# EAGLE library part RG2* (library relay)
HIGH FREQUENCY RELAYS WITH 1C AND 2C CONTACTS NAiS Source: http://www.mew-europe.com/.. en_ds_61302_0000.pdf
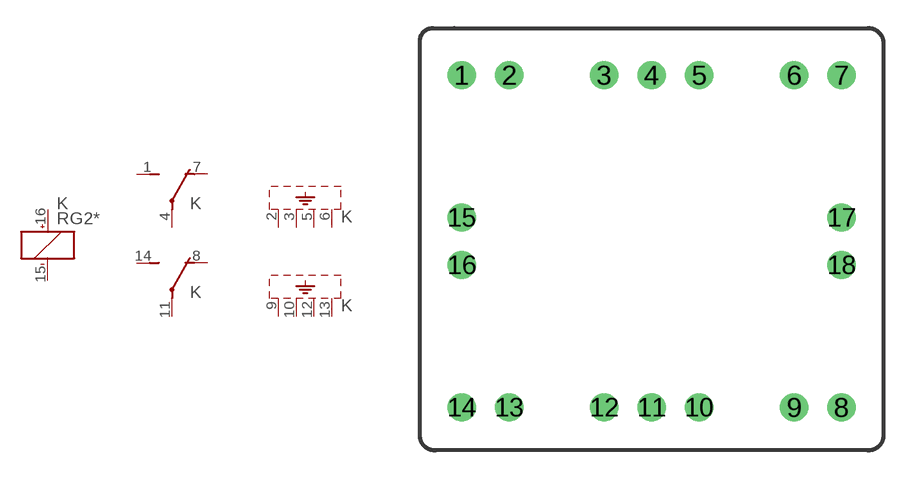
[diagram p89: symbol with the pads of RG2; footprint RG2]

Designator prefix K; gates A=K+- 1=U 2=U S1=SHIELD-4 S2=SHIELD-4

## RG2-3V (OC_FARNELL: unknown; OC_NEWARK: unknown), RG2-5V (OC_FARNELL: unknown; OC_NEWARK: unknown), RG2-6V (OC_FARNELL: unknown; OC_NEWARK: unknown), RG2-9V (OC_FARNELL: unknown; OC_NEWARK: unknown), RG2-12V (OC_FARNELL: unknown; OC_NEWARK: unknown), RG2-24V (OC_FARNELL: unknown; OC_NEWARK: unknown), RG2-48V (OC_FARNELL: unknown; OC_NEWARK: unknown), RG2T-3V (OC_FARNELL: unknown; OC_NEWARK: unknown), RG2T-5V (OC_FARNELL: unknown; OC_NEWARK: unknown), RG2T-6V (OC_FARNELL: unknown; OC_NEWARK: unknown), RG2T-9V (OC_FARNELL: unknown; OC_NEWARK: unknown), RG2T-12V (OC_FARNELL: unknown; OC_NEWARK: unknown), RG2T-24V (OC_FARNELL: unknown; OC_NEWARK: unknown), RG2T-48V (OC_FARNELL: unknown; OC_NEWARK: unknown)  [RG2]
1  1:S  pas
2  S1:SH  pas
3  S1:SH  pas
4  1:P  pas
5  S1:SH  pas
6  S1:SH  pas
7  1:O  pas
8  2:O  pas
9  S2:SH  pas
10  S2:SH  pas
11  2:P  pas
12  S2:SH  pas
13  S2:SH  pas
14  2:S  pas
15  A:-  pas
16  A:+  pas

## RG2-3V-L (OC_FARNELL: unknown; OC_NEWARK: unknown), RG2-5V-L (OC_FARNELL: unknown; OC_NEWARK: unknown), RG2-6V-L (OC_FARNELL: unknown; OC_NEWARK: unknown), RG2-9V-L (OC_FARNELL: unknown; OC_NEWARK: unknown), RG2-12V-L (OC_FARNELL: unknown; OC_NEWARK: unknown), RG2-24V-L (OC_FARNELL: unknown; OC_NEWARK: unknown), RG2-48V-L (OC_FARNELL: unknown; OC_NEWARK: unknown)  [RG2]
1  1:S  pas
2  S1:SH  pas
3  S1:SH  pas
4  1:P  pas
5  S1:SH  pas
6  S1:SH  pas
7  1:O  pas
8  2:O  pas
9  S2:SH  pas
10  S2:SH  pas
11  2:P  pas
12  S2:SH  pas
13  S2:SH  pas
14  2:S  pas
15  A:+  pas
16  A:-  pas

## RG2-3VT-L (OC_FARNELL: unknown; OC_NEWARK: unknown), RG2-5VT-L (OC_FARNELL: unknown; OC_NEWARK: unknown), RG2-6VT-L (OC_FARNELL: unknown; OC_NEWARK: unknown), RG2-9VT-L (OC_FARNELL: unknown; OC_NEWARK: unknown), RG2-12VT-L (OC_FARNELL: unknown; OC_NEWARK: unknown), RG2-24VT-L (OC_FARNELL: unknown; OC_NEWARK: unknown), RG2-48VT-L (OC_FARNELL: unknown; OC_NEWARK: unknown)  [RG2]
Pads as for RG2

## Footprint RG2 (pad centres in mm)
HIGH FREQUENCY RELAYS WITH 1C AND 2C CONTACTS NAiS Source: http://www.mew-europe.com/.. en_ds_61302_0000.pdf
drill 1 round: 1 -10.16,8.89; 2 -7.62,8.89; 3 -2.54,8.89; 4 0,8.89; 5 2.54,8.89; 6 7.62,8.89; 7 10.16,8.89; 8 10.16,-8.89; 9 7.62,-8.89; 10 2.54,-8.89; 11 0,-8.89; 12 -2.54,-8.89; 13 -7.62,-8.89; 14 -10.16,-8.89; 15 -10.16,1.27; 16 -10.16,-1.27; 17 10.16,1.27; 18 10.16,-1.27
